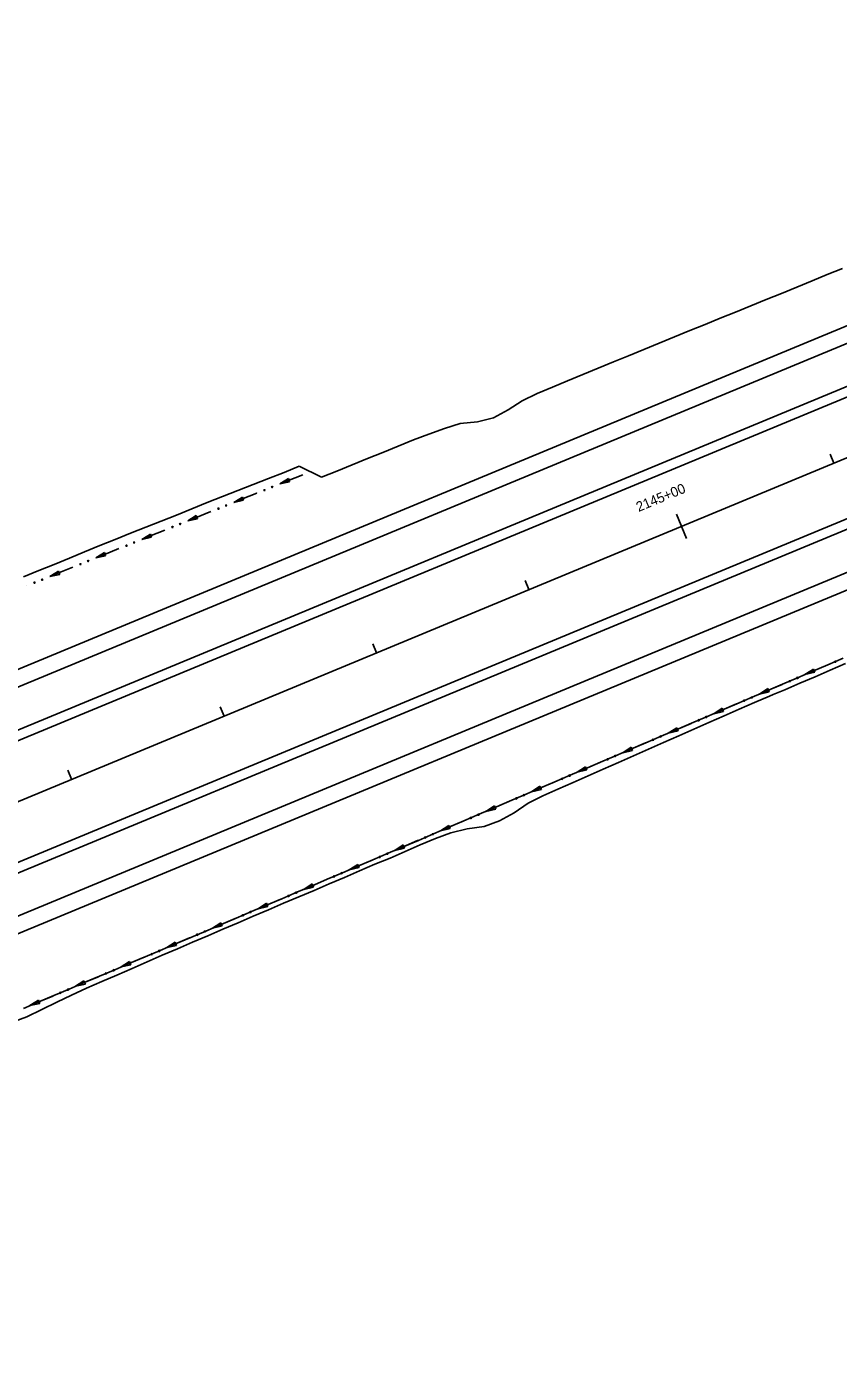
# Model space of a CAD drawing. Extents: x 1611108 to 1749517, y 619561 to 797725.
# Drawn here: x 1719999 to 1720490, y 767079 to 767893 of the extents above; entities that cross this region are included whole.
import ezdxf

# ---------------------------------------------------------------- set-up
doc = ezdxf.new("R2010")
doc.units = 0
for name, color, linetype in [('R_Ditch', 7, 'Continuous'), ('R_Horz Alg', 7, 'Continuous'), ('R_Horz Alg Stationing', 7, 'Continuous'), ('R_Proposed Const Limits', 7, 'Continuous'), ('R_Proposed Road', 7, 'Continuous')]:
    doc.layers.add(name, color=color, linetype=linetype)

msp = doc.modelspace()

# ---------------------------------------------------------------- linework, layer by layer
at = {"layer": 'R_Ditch'}
for p, q in [((1720157.26, 767619.23), (1720152.09, 767616.02)), ((1720152.09, 767616.02), (1720158.05, 767617.27)), ((1720158.05, 767617.27), (1720157.26, 767619.23)), ((1720129.38, 767608.06), (1720124.2, 767604.84)), ((1720130.17, 767606.1), (1720129.38, 767608.06)), ((1720124.2, 767604.84), (1720130.17, 767606.1)), ((1720101.5, 767596.87), (1720096.33, 767593.65)), ((1720096.33, 767593.65), (1720102.29, 767594.91)), ((1720102.29, 767594.91), (1720101.5, 767596.87)), ((1720073.63, 767585.67), (1720068.46, 767582.45)), ((1720068.46, 767582.45), (1720074.42, 767583.7)), ((1720074.42, 767583.7), (1720073.63, 767585.67)), ((1720045.77, 767574.45), (1720040.6, 767571.23)), ((1720040.6, 767571.23), (1720046.56, 767572.49)), ((1720046.56, 767572.49), (1720045.77, 767574.45)), ((1720017.91, 767563.22), (1720012.74, 767559.99)), ((1720012.74, 767559.99), (1720018.7, 767561.25)), ((1720018.7, 767561.25), (1720017.91, 767563.22)), ((1720475.41, 767503.9), (1720470.31, 767500.56)), ((1720470.31, 767500.56), (1720476.25, 767501.95)), ((1720476.25, 767501.95), (1720475.41, 767503.9)), ((1720447.8, 767492.07), (1720442.7, 767488.74)), ((1720442.7, 767488.74), (1720448.63, 767490.13)), ((1720448.63, 767490.13), (1720447.8, 767492.07)), ((1720420.19, 767480.24), (1720415.09, 767476.91)), ((1720415.09, 767476.91), (1720421.02, 767478.3)), ((1720421.02, 767478.3), (1720420.19, 767480.24)), ((1720392.58, 767468.42), (1720387.48, 767465.08)), ((1720387.48, 767465.08), (1720393.41, 767466.47)), ((1720393.41, 767466.47), (1720392.58, 767468.42)), ((1720364.97, 767456.59), (1720359.87, 767453.25)), ((1720359.87, 767453.25), (1720365.8, 767454.64)), ((1720365.8, 767454.64), (1720364.97, 767456.59)), ((1720337.35, 767444.76), (1720332.26, 767441.43)), ((1720338.19, 767442.82), (1720337.35, 767444.76)), ((1720332.26, 767441.43), (1720338.19, 767442.82)), ((1720309.74, 767432.93), (1720304.64, 767429.6)), ((1720304.64, 767429.6), (1720310.58, 767430.99)), ((1720310.58, 767430.99), (1720309.74, 767432.93)), ((1720282.13, 767421.11), (1720277.03, 767417.77)), ((1720282.96, 767419.16), (1720282.13, 767421.11)), ((1720277.03, 767417.77), (1720282.96, 767419.16)), ((1720254.52, 767409.28), (1720249.42, 767405.95)), ((1720249.42, 767405.95), (1720255.35, 767407.33)), ((1720255.35, 767407.33), (1720254.52, 767409.28)), ((1720226.91, 767397.46), (1720221.8, 767394.13)), ((1720227.74, 767395.52), (1720226.91, 767397.46)), ((1720221.8, 767394.13), (1720227.74, 767395.52)), ((1720199.28, 767385.66), (1720194.18, 767382.33)), ((1720194.18, 767382.33), (1720200.12, 767383.71)), ((1720200.12, 767383.71), (1720199.28, 767385.66)), ((1720171.66, 767373.87), (1720166.55, 767370.54)), ((1720166.55, 767370.54), (1720172.49, 767371.92)), ((1720172.49, 767371.92), (1720171.66, 767373.87)), ((1720144.03, 767362.09), (1720138.92, 767358.77)), ((1720138.92, 767358.77), (1720144.85, 767360.14)), ((1720144.85, 767360.14), (1720144.03, 767362.09)), ((1720116.39, 767350.33), (1720111.28, 767347.01)), ((1720111.28, 767347.01), (1720117.21, 767348.38)), ((1720117.21, 767348.38), (1720116.39, 767350.33)), ((1720088.74, 767338.59), (1720083.63, 767335.27)), ((1720083.63, 767335.27), (1720089.57, 767336.64)), ((1720089.57, 767336.64), (1720088.74, 767338.59)), ((1720061.09, 767326.85), (1720055.98, 767323.54)), ((1720055.98, 767323.54), (1720061.91, 767324.91)), ((1720061.91, 767324.91), (1720061.09, 767326.85)), ((1720033.43, 767315.14), (1720028.32, 767311.83)), ((1720034.25, 767313.19), (1720033.43, 767315.14)), ((1720028.32, 767311.83), (1720034.25, 767313.19)), ((1720005.76, 767303.44), (1720000.65, 767300.13)), ((1720000.65, 767300.13), (1720006.59, 767301.49)), ((1720006.59, 767301.49), (1720005.76, 767303.44))]:
    msp.add_line(p, q, dxfattribs=at)
for points in [[(1720166.01, 767621.6), (1720156.73, 767617.88), (1720152.09, 767616.02)], [(1720138.13, 767610.43), (1720128.88, 767606.72), (1720124.2, 767604.84)], [(1720138.16, 767610.44), (1720138.16, 767610.44), (1720138.13, 767610.43)], [(1720110.25, 767599.24), (1720101.04, 767595.54), (1720096.33, 767593.65)], [(1720110.28, 767599.26), (1720110.25, 767599.24)], [(1720082.38, 767588.04), (1720073.2, 767584.35), (1720068.46, 767582.45)], [(1720082.41, 767588.06), (1720082.38, 767588.04)], [(1720054.51, 767576.83), (1720045.37, 767573.15), (1720040.6, 767571.23)], [(1720054.54, 767576.85), (1720054.51, 767576.83)], [(1720026.65, 767565.6), (1720017.54, 767561.93), (1720012.74, 767559.99)], [(1720026.68, 767565.62), (1720026.65, 767565.6)], [(1719998.83, 767554.37), (1719998.8, 767554.36)], [(1719996.78, 767298.49), (1720005.99, 767302.39), (1720015.2, 767306.28), (1720024.41, 767310.17), (1720033.62, 767314.07), (1720042.83, 767317.97), (1720052.04, 767321.87), (1720061.24, 767325.77), (1720070.45, 767329.68), (1720079.66, 767333.58), (1720088.86, 767337.49), (1720098.07, 767341.4), (1720107.27, 767345.31), (1720116.47, 767349.22), (1720125.68, 767353.13), (1720134.88, 767357.05), (1720144.08, 767360.96), (1720153.28, 767364.88), (1720162.48, 767368.8), (1720171.68, 767372.72), (1720180.88, 767376.65), (1720190.08, 767380.57), (1720199.28, 767384.5), (1720208.47, 767388.43), (1720217.67, 767392.36), (1720226.86, 767396.29), (1720236.06, 767400.22), (1720245.25, 767404.16), (1720254.45, 767408.1), (1720263.64, 767412.04), (1720272.83, 767415.97), (1720282.02, 767419.91), (1720291.22, 767423.85), (1720300.41, 767427.79), (1720309.6, 767431.72), (1720318.79, 767435.66), (1720327.99, 767439.6), (1720337.18, 767443.54), (1720346.37, 767447.47), (1720355.57, 767451.41), (1720364.76, 767455.35), (1720373.95, 767459.29), (1720383.15, 767463.22), (1720392.34, 767467.16), (1720401.53, 767471.1), (1720410.72, 767475.04), (1720419.92, 767478.98), (1720429.11, 767482.91), (1720438.3, 767486.85), (1720447.5, 767490.79), (1720449.64, 767491.71), (1720456.69, 767494.73), (1720465.88, 767498.66), (1720475.07, 767502.6), (1720484.27, 767506.54), (1720493.46, 767510.48)], [(1720484.1, 767506.47), (1720475.07, 767502.6), (1720470.31, 767500.56)], [(1720484.14, 767506.48), (1720484.1, 767506.47)], [(1720456.49, 767494.64), (1720449.64, 767491.71), (1720447.5, 767490.79), (1720442.7, 767488.74)], [(1720456.52, 767494.66), (1720456.49, 767494.64)], [(1720428.88, 767482.81), (1720419.92, 767478.98), (1720415.09, 767476.91)], [(1720428.91, 767482.83), (1720428.88, 767482.81)], [(1720401.27, 767470.99), (1720392.34, 767467.16), (1720387.48, 767465.08)], [(1720401.3, 767471), (1720401.27, 767470.99)], [(1720373.66, 767459.16), (1720364.76, 767455.35), (1720359.87, 767453.25)], [(1720373.69, 767459.17), (1720373.66, 767459.16)], [(1720346.04, 767447.33), (1720337.18, 767443.54), (1720332.26, 767441.43)], [(1720346.08, 767447.35), (1720346.04, 767447.33)], [(1720318.43, 767435.51), (1720309.6, 767431.72), (1720304.64, 767429.6)], [(1720318.47, 767435.52), (1720318.43, 767435.51)], [(1720290.82, 767423.68), (1720282.02, 767419.91), (1720277.03, 767417.77)], [(1720290.86, 767423.69), (1720290.82, 767423.68)], [(1720263.21, 767411.85), (1720254.45, 767408.1), (1720249.42, 767405.95)], [(1720263.24, 767411.87), (1720263.21, 767411.85)], [(1720235.6, 767400.03), (1720226.86, 767396.29), (1720221.8, 767394.13)], [(1720235.63, 767400.04), (1720235.6, 767400.03)], [(1720207.98, 767388.22), (1720199.28, 767384.5), (1720194.18, 767382.33)], [(1720208.01, 767388.23), (1720207.98, 767388.22)], [(1720180.35, 767376.42), (1720171.68, 767372.72), (1720166.55, 767370.54)], [(1720180.39, 767376.44), (1720180.35, 767376.42)], [(1720152.72, 767364.64), (1720144.08, 767360.96), (1720138.92, 767358.77)], [(1720152.75, 767364.66), (1720152.72, 767364.64)], [(1720125.08, 767352.88), (1720116.47, 767349.22), (1720111.28, 767347.01)], [(1720125.12, 767352.89), (1720125.08, 767352.88)], [(1720097.44, 767341.13), (1720088.86, 767337.49), (1720083.63, 767335.27)], [(1720097.47, 767341.14), (1720097.44, 767341.13)], [(1720069.79, 767329.39), (1720061.24, 767325.77), (1720055.98, 767323.54)], [(1720069.82, 767329.41), (1720069.79, 767329.39)], [(1720042.13, 767317.67), (1720033.62, 767314.07), (1720028.32, 767311.83)], [(1720042.16, 767317.69), (1720042.13, 767317.67)], [(1720014.46, 767305.97), (1720005.99, 767302.39), (1720000.65, 767300.13)], [(1720014.5, 767305.98), (1720014.47, 767305.97)]]:
    msp.add_lwpolyline(points, dxfattribs=at)
for centre in [(1720142.8, 767612.26), (1720147.45, 767614.13), (1720114.92, 767601.08), (1720119.57, 767602.95), (1720091.7, 767591.75), (1720087.05, 767589.88), (1720059.18, 767578.67), (1720063.83, 767580.54), (1720031.32, 767567.45), (1720035.97, 767569.32), (1720003.47, 767556.21), (1720008.11, 767558.08), (1720488.73, 767508.41), (1720461.12, 767496.59), (1720465.73, 767498.56), (1720438.11, 767486.73), (1720433.51, 767484.76), (1720405.9, 767472.93), (1720410.5, 767474.9), (1720378.29, 767461.1), (1720382.89, 767463.08), (1720350.67, 767449.28), (1720355.28, 767451.25), (1720323.06, 767437.45), (1720327.67, 767439.42), (1720295.45, 767425.62), (1720300.06, 767427.6), (1720267.84, 767413.8), (1720272.44, 767415.77), (1720244.83, 767403.94), (1720240.23, 767401.97), (1720212.61, 767390.16), (1720217.22, 767392.13), (1720189.59, 767380.33), (1720184.98, 767378.36), (1720157.35, 767366.58), (1720161.96, 767368.54), (1720134.33, 767356.77), (1720129.72, 767354.81), (1720102.07, 767343.06), (1720106.68, 767345.02), (1720074.42, 767331.32), (1720079.04, 767333.28), (1720046.77, 767319.6), (1720051.38, 767321.55), (1720019.1, 767307.89), (1720023.72, 767309.84)]:
    msp.add_circle(centre, 0.375, dxfattribs=at)
at = {"layer": 'R_Horz Alg'}
msp.add_line((1715964.86, 765755.05), (1723860.62, 769025.58), dxfattribs=at)
at = {"layer": 'R_Horz Alg Stationing'}
for points in [[(1720485.56, 767634.08), (1720487.85, 767628.54)], [(1720392.4, 767597.66), (1720398.53, 767582.88)], [(1720300.78, 767557.54), (1720303.08, 767552)], [(1720208.39, 767519.28), (1720210.69, 767513.73)], [(1720116.01, 767481.01), (1720118.3, 767475.46)], [(1720023.62, 767442.74), (1720025.91, 767437.2)]]:
    msp.add_lwpolyline(points, dxfattribs=at)
at = {"layer": 'R_Proposed Const Limits'}
msp.add_line((1720163.91, 767626.68), (1720177.45, 767620.12), dxfattribs=at)
for points in [[(1720177.45, 767620.12), (1720186.73, 767623.83), (1720195.98, 767627.64), (1720205.26, 767631.37), (1720214.54, 767635.1), (1720223.8, 767638.86), (1720233.05, 767642.66), (1720242.4, 767646.22), (1720251.84, 767649.57), (1720261.44, 767652.52), (1720271.81, 767653.61), (1720281.64, 767656.02), (1720290.47, 767660.83), (1720298.99, 767666.38), (1720308.04, 767670.68), (1720317.25, 767674.58), (1720326.46, 767678.47), (1720335.68, 767682.33), (1720344.94, 767686.12), (1720354.21, 767689.87), (1720363.48, 767693.62), (1720372.7, 767697.49), (1720381.94, 767701.32), (1720391.21, 767705.07), (1720400.48, 767708.82), (1720409.75, 767712.57), (1720419.02, 767716.32), (1720428.29, 767720.08), (1720437.55, 767723.85), (1720446.81, 767727.63), (1720456.07, 767731.41), (1720465.32, 767735.19), (1720474.58, 767738.97), (1720483.85, 767742.73), (1720493.11, 767746.51)], [(1719996.78, 767559.8), (1720006.04, 767563.56), (1720015.31, 767567.32), (1720024.57, 767571.08), (1720033.83, 767574.87), (1720043.08, 767578.66), (1720052.34, 767582.44), (1720061.63, 767586.15), (1720070.95, 767589.77), (1720080.28, 767593.4), (1720089.54, 767597.15), (1720098.79, 767600.97), (1720108.03, 767604.78), (1720117.35, 767608.42), (1720126.67, 767612.05), (1720135.99, 767615.68), (1720145.31, 767619.31), (1720154.63, 767622.94), (1720163.91, 767626.68)], [(1719989.54, 767289.84), (1719998.88, 767293.41), (1720007.85, 767297.88), (1720016.87, 767302.24), (1720025.92, 767306.53), (1720035.03, 767310.65), (1720044.2, 767314.66), (1720053.36, 767318.66), (1720062.53, 767322.67), (1720071.7, 767326.65), (1720080.87, 767330.66), (1720090.05, 767334.62), (1720099.25, 767338.55), (1720108.44, 767342.48), (1720117.64, 767346.42), (1720126.83, 767350.35), (1720136.03, 767354.28), (1720145.22, 767358.2), (1720154.42, 767362.13), (1720163.62, 767366.06), (1720172.9, 767369.79), (1720182.05, 767373.83), (1720191.22, 767377.82), (1720200.4, 767381.79), (1720209.58, 767385.74), (1720218.87, 767389.46), (1720228.01, 767393.53), (1720237.18, 767397.52), (1720246.44, 767401.29), (1720255.8, 767404.84), (1720265.68, 767407.1), (1720275.89, 767408.59), (1720285.29, 767412.02), (1720294.1, 767416.88), (1720302.5, 767422.74), (1720311.46, 767427.24), (1720320.65, 767431.19), (1720329.8, 767435.21), (1720338.96, 767439.24), (1720348.11, 767443.27), (1720357.26, 767447.32), (1720366.41, 767451.36), (1720375.56, 767455.41), (1720384.69, 767459.51), (1720393.83, 767463.56), (1720402.99, 767467.58), (1720412.15, 767471.61), (1720421.3, 767475.63), (1720430.47, 767479.63), (1720439.65, 767483.59), (1720448.85, 767487.51), (1720451, 767488.43), (1720458.05, 767491.44), (1720467.25, 767495.36), (1720476.45, 767499.29), (1720485.63, 767503.26), (1720494.82, 767507.2)]]:
    msp.add_lwpolyline(points, dxfattribs=at)
at = {"layer": 'R_Proposed Road'}
for p, q in [((1715936.54, 765823.42), (1723832.3, 769093.95)), ((1715940.37, 765814.18), (1723836.12, 769084.71)), ((1715949.55, 765792.01), (1723845.31, 769062.54)), ((1715951.85, 765786.47), (1723847.6, 769056.99)), ((1715977.87, 765723.64), (1723873.63, 768994.17)), ((1715980.17, 765718.1), (1723875.92, 768988.63)), ((1715989.35, 765695.93), (1723885.11, 768966.45)), ((1715993.18, 765686.69), (1723888.93, 768957.22))]:
    msp.add_line(p, q, dxfattribs=at)

# ---------------------------------------------------------------- texts
at = {"layer": 'R_Horz Alg Stationing'}
msp.add_text('2145+00', height=6, rotation=22.5, dxfattribs=at).set_placement((1720369.5, 767599))

doc.saveas('drawing.dxf')
